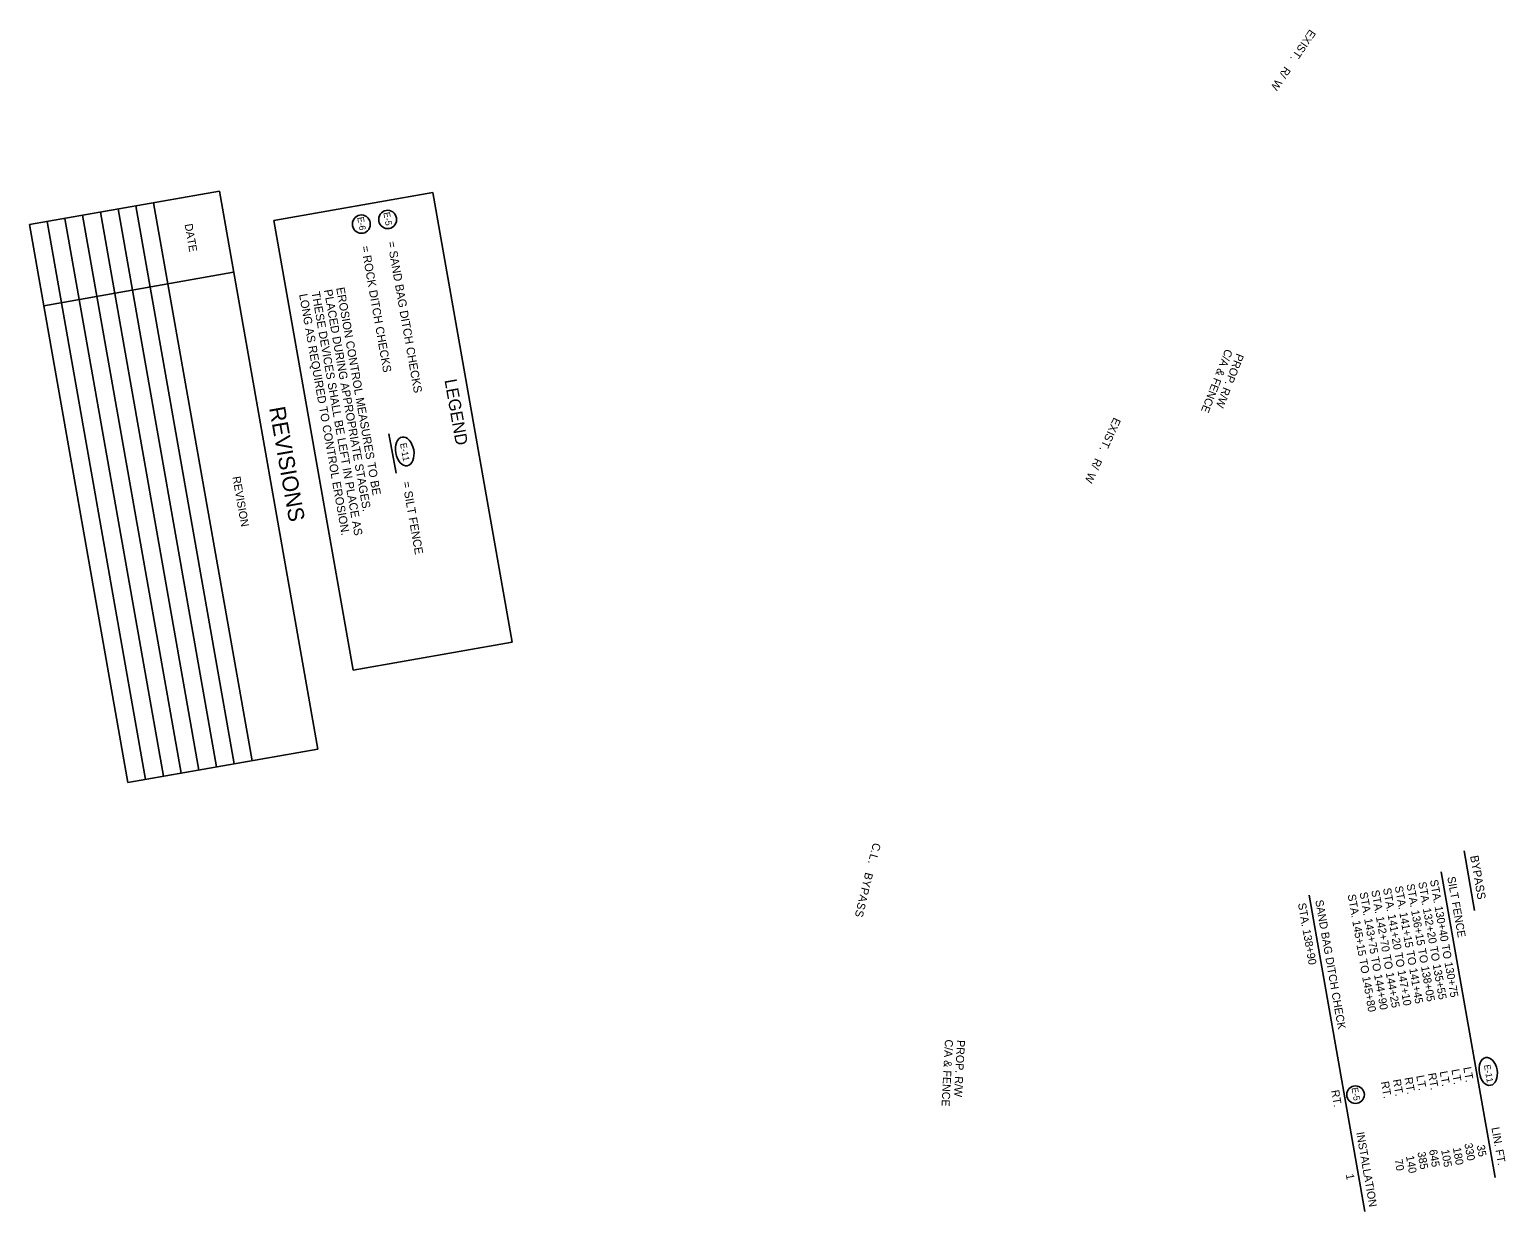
# Model space of a CAD drawing. Extents: x 979995 to 981206, y 1838837 to 1840486.
# Drawn here: x 979995 to 981102, y 1839600 to 1840486 of the extents above; entities that cross this region are included whole.
import ezdxf

# ---------------------------------------------------------------- set-up
doc = ezdxf.new("R2010")
doc.units = 0
for name, color, linetype in [('1', 7, 'Continuous'), ('44', 7, 'Continuous'), ('G-Border-Sheet', 7, 'Continuous'), ('Level 1', 7, 'Continuous'), ('Level 44', 7, 'Continuous'), ('R_Draft', 7, 'Continuous')]:
    doc.layers.add(name, color=color, linetype=linetype)

msp = doc.modelspace()

# ---------------------------------------------------------------- linework, layer by layer
at = {"layer": '1'}
msp.add_circle((980989.5, 1839687.3), 6.61, dxfattribs=at)
msp.add_ellipse((981089, 1839704.7), major_axis=(1.8, -10.4), ratio=0.638788, dxfattribs=at)
at = {"layer": '44'}
for p, q in [((981070.9, 1839870.3), (981078.8, 1839825.5)), ((981053.8, 1839854.5), (981094.2, 1839625.2)), ((980954.8, 1839837), (980996.6, 1839599.7))]:
    msp.add_line(p, q, dxfattribs=at)
at = {"layer": 'G-Border-Sheet'}
for p, q in [((980178.3, 1840343), (980297.5, 1840364)), ((980297.5, 1840364), (980357, 1840026.6)), ((980178.3, 1840343), (980237.8, 1840005.6)), ((980237.8, 1840005.6), (980357, 1840026.6))]:
    msp.add_line(p, q, dxfattribs=at)
at = {"layer": 'Level 1'}
for centre, major_axis, ratio in [((980244, 1840340.3), (-1.19, 6.78), 0.97521), ((980263.7, 1840343.8), (-1.19, 6.78), 0.97521), ((980276.5, 1840169.8), (1.9, -10.8), 0.622952)]:
    msp.add_ellipse(centre, major_axis=major_axis, ratio=ratio, dxfattribs=at)
at = {"layer": 'Level 44'}
msp.add_lwpolyline([(980264.7, 1840183), (980270, 1840153.4)], dxfattribs=at)
at = {"layer": 'R_Draft'}
for p, q in [((980137.5, 1840365), (979995.2, 1840339.9)), ((980137.5, 1840365), (980211.3, 1839946.5)), ((980074.9, 1840354), (980148.7, 1839935.5)), ((980088.2, 1840356.3), (980162, 1839937.8)), ((980008.4, 1840342.3), (980082.2, 1839923.7)), ((980021.7, 1840344.6), (980095.5, 1839926.1)), ((980035, 1840347), (980108.8, 1839928.4)), ((980048.3, 1840349.3), (980122.1, 1839930.8)), ((980048.3, 1840349.3), (980122.1, 1839930.8)), ((980061.6, 1840351.7), (980135.4, 1839933.1)), ((979995.2, 1840339.9), (980069, 1839921.4)), ((980148.2, 1840304.2), (980005.9, 1840279.1)), ((980211.3, 1839946.5), (980069, 1839921.4))]:
    msp.add_line(p, q, dxfattribs=at)

# ---------------------------------------------------------------- texts
at = {"layer": '1'}
for s, p in [('E-11', (981085.8, 1839709.4)), ('E-5 ', (980986.5, 1839692.3))]:
    msp.add_text(s, height=4.8, rotation=280, dxfattribs=at).set_placement(p)
at = {"layer": '44'}
for s, height, p in [('BYPASS', 6.25, (981075.4, 1839866.2)), ('STA. 136+15 TO 138+05', 6, (981027.7, 1839845)), ('STA. 132+20 TO 135+55', 6, (981036.5, 1839846.5)), ('STA. 130+40 TO 130+75', 6, (981045.3, 1839848.1)), ('SILT FENCE      ', 6, (981058.3, 1839850.4)), ('SAND BAG DITCH CHECK', 6, (980959.3, 1839832.9)), ('STA. 145+15 TO 145+80', 6, (980983.6, 1839837.2)), ('STA. 143+75 TO 144+90', 6, (980992.5, 1839838.8)), ('STA. 142+70 TO 144+25', 6, (981001.3, 1839840.3)), ('STA. 141+20 TO 147+10', 6, (981010.1, 1839841.9)), ('STA. 141+15 TO 141+45', 6, (981018.9, 1839843.4)), ('STA. 138+90', 6, (980946.3, 1839830.6)), ('RT.', 6, (981026.2, 1839699.9)), ('LT.', 6, (981035, 1839701.4)), ('RT.', 6, (981043.8, 1839703.1)), ('LT.', 6, (981052.6, 1839704.5)), ('LT.', 6, (981061.4, 1839706)), ('LT.', 6, (981070.3, 1839707.6)), ('RT.', 6, (980971.2, 1839690.3)), ('RT.', 6, (981008.5, 1839696.8)), ('RT.', 6, (981017.4, 1839698.4)), ('INSTALLATION', 6, (980990, 1839658.8)), ('LIN. FT.', 6, (981091.4, 1839662.4)), ('645', 6, (981044.6, 1839645.7)), ('105', 6, (981053.7, 1839645.7)), ('180', 6, (981062.5, 1839647.3)), ('330', 6, (981071.1, 1839650.5)), ('35', 6, (981080.4, 1839649.1)), ('70', 6, (981018.7, 1839638.5)), ('140', 6, (981027.3, 1839641.1)), ('385', 6, (981035.9, 1839644)), ('1', 6, (980982.2, 1839627.4))]:
    msp.add_text(s, height=height, rotation=280, dxfattribs=at).set_placement(p)
at = {"layer": 'Level 1'}
for s, height, p in [('E-6 ', 4.88, (980240.9, 1840345.3)), ('E-5 ', 4.88, (980260.5, 1840348.9)), ('= ROCK DITCH CHECKS', 6.25, (980243.8, 1840323.5)), ('= SAND BAG DITCH CHECKS', 6.25, (980263.5, 1840326.9)), ('LONG AS REQUIRED TO CONTROL EROSION.', 6.25, (980197.3, 1840287.5)), ('THESE DEVICES SHALL BE LEFT IN PLACE AS ', 6.25, (980206.6, 1840289.2)), ('PLACED DURING APPROPRIATE STAGES. ', 6.25, (980215.9, 1840290.8)), ('EROSION CONTROL MEASURES TO BE', 6.25, (980225.1, 1840292.4)), ('E-11 ', 4.88, (980273, 1840175.7)), ('= SILT FENCE', 6.25, (980274.7, 1840146.7))]:
    msp.add_text(s, height=height, rotation=280, dxfattribs=at).set_placement(p)
at = {"layer": 'Level 44'}
msp.add_text('LEGEND', height=9.14, rotation=280, dxfattribs=at).set_placement((980306.3, 1840223.3))
at = {"layer": 'R_Draft'}
for s, height, rotation, p in [('E', 6, 235.8612, (980955.2, 1840486.8)), ('S', 6, 235.8612, (980947.9, 1840476)), ('I', 6, 235.8612, (980949, 1840477.6)), ('X', 6, 235.8612, (980952.2, 1840482.4)), ('.', 6, 235.8612, (980941.4, 1840466.4)), ('T', 6, 235.8612, (980944.7, 1840471.3)), ('/', 6, 235.8612, (980933.2, 1840454.3)), ('R', 6, 235.8612, (980936.4, 1840459)), ('W', 6, 235.8612, (980929.9, 1840449.5)), ('DATE', 6, 280, (980111.4, 1840340.1)), ('C/A & FENCE', 6, 248.4526, (980892, 1840247.1)), ('PROP. R/W', 6, 248.4526, (980900.4, 1840243.8)), ('REVISIONS', 12, 280, (980174.8, 1840202.4)), ('X', 6, 245.3622, (980806.1, 1840190.8)), ('E', 6, 245.3622, (980808.3, 1840195.7)), ('T', 6, 245.3622, (980800.5, 1840178.6)), ('S', 6, 245.3622, (980802.9, 1840183.8)), ('I', 6, 245.3622, (980803.7, 1840185.6)), ('.', 6, 245.3622, (980798.1, 1840173.3)), ('/', 6, 245.3622, (980792, 1840160.1)), ('R', 6, 245.3622, (980794.3, 1840165.2)), ('REVISION', 6, 280, (980147.3, 1840150.6)), ('W', 6, 245.3622, (980789.5, 1840154.7)), ('L', 6, 255.0907, (980625.7, 1839868.3)), ('.', 6, 254.9446, (980626.4, 1839871.1)), ('C', 6, 254.6619, (980627.9, 1839876.6)), ('.', 6, 255.3593, (980624.3, 1839863.1)), ('Y', 6, 256.0873, (980620.6, 1839848.9)), ('B', 6, 255.8046, (980622, 1839854.4)), ('A', 6, 256.6575, (980617.9, 1839837.7)), ('P', 6, 256.3748, (980619.2, 1839843.2)), ('S', 6, 257.2324, (980615.2, 1839826.4)), ('S', 6, 256.9496, (980616.5, 1839832)), ('C/A & FENCE', 6, 266.993, (980681.7, 1839728.8)), ('PROP. R/W', 6, 266.993, (980690.7, 1839728.4))]:
    msp.add_text(s, height=height, rotation=rotation, dxfattribs=at).set_placement(p)

doc.saveas('drawing.dxf')
